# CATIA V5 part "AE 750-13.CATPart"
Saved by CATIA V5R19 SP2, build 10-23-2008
Part number: AE 750-13
Bounding box of the stored display mesh (mm): x -24.865 to 24.865, y -24.997 to 24.997, z 0 to 75.4
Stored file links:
  C:\Users\Bora\Desktop\3D Katı model\AE serisi\AE 750\AE 750-13.CATPart
  C:\Program Files\Dassault Systemes\B19\intel_a\reffiles\standard\MetricThickPitch.txt
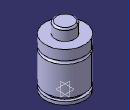
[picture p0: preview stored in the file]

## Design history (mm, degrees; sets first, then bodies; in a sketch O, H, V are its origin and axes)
Body1 (main body)
  Sketch1 on yz-plane, origin (0, 0, 0), H (0, 1, 0), V (0, 0, 1)
    point P1 (25, 44.9)
    point P8 (25, 48.9)
    point P9 (12.5, 73.4)
    point P11 (12.5, 73.4)
    point P13 (25, 48.9)
    point P14 (25, 44.9)
    line L1 (25, 44.9) -> (25, 8)
    line L2 (25, 4) -> (25, 0)
    line L3 (21.5, 8) -> (21.5, 4)
    line L4 (25, 61.4) -> (25, 48.9)
    line L5 (12.5, 73.4) -> (12.5, 61.4)
    arc A1 centre (10.5, 73.4) radius 2 from (12.5, 73.4) to (10.5, 75.4) ccw
    arc A2 centre (25, 46.9) radius 2 from (25, 48.9) to (25, 44.9) ccw
    line L6 (10.5, 75.4) -> (0, 75.4)
    point P15 (0, 75.4)
    line L7 (12.5, 61.4) -> (25, 61.4)
    line L8 (0, 0) -> (25, 0)
    line L9 (21.5, 8) -> (25, 8)
    line L10 (21.5, 4) -> (25, 4)
    tangency: L6 A1
    coincidence: P15 V, P1 P14, P8 P13, P9 P11
    horizontal: L7 H, L8 H, L9 H, L10 H
  Shaft1: profile Sketch1, axis Sketch1.V, angle 360
  Sketch2 on face of Shaft1 from Sketch1.L8, origin (0, 0, 0), H (1, 0, 0), V (0, -1, 0)
    point P1 (10, 0)
    distance P1 V = 10
  Hole1: placed by Sketch2, at (10, 0, 0) direction (0, 0, 1), diameter 6.647, depth 13, threaded "M8", thread diameter 8, thread depth 13, pitch 1.25
  CircPattern1: of Hole1, instances 2, angular step 180, axis from xy-plane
